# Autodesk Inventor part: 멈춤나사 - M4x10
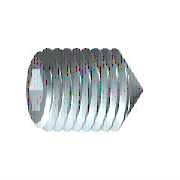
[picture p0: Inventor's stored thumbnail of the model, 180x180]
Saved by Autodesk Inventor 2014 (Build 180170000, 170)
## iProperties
Created: 2012-02
Part Number: 멈춤나사 - M4x10
Material: 강철, 연강
Description: 6각 소켓 머리 없는 멈춤 나사
Document SubType Name: Modeling
Standard: KS B 1028
Designer: mduedu
Standards Organization: KS
Language: ko-KR
Size Designation: 원추점 M4x10
Categories: <MemberInstance><Categories><Category DisplayName="조임쇠" InternalName="e4da775c-781d-43d5-af7c-5136215cf5a6" Mnemonic="FSTN"><Category DisplayName="볼트" InternalN
Density: 7.86 g/cm^3
Appearance: 강철
Mass: 0.792069 g
Surface Area: 1.48192 cm^2
Volume: 0.100772 cm^3
Author: mduedu
IsCustomPart: 1
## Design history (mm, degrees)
sketch "스케치1"
  geometry: L1 (0, 0)-(6.833, 0); L2 (10, 1.155)-(10, 2); L3 (10, 2)-(0, 2); L4 (10, 1.155)-(7.5, 1.155); L5 (7.5, 1.155)-(6.833, 0); L6 (0, -0.4)-(0, 2.4) reference; L7 (0, 2)-(0, 0)
  constraints: 13 end point, 3 parallel, 1 collinear, 1 perpendicular, 1 point on line
  dimensions: "d0" = 2.5 distance of L2.start L4.end (= INTI); "d1" = 60 deg angle of L5 L1; "d2" = 4 diameter of L3 L1 (= NND); "d3" = 2.3094 diameter of L4 L1 (= 1.1547 x SW); "d5" = 10 distance from line of L2 L3.end (= NLG)
revolve "본체" sketch "스케치1" stored, may be unused: angle "d6" = 90 deg
sketch "스케치2"
  geometry: L1 (-0.577, 1)-(0.577, 1); L2 (0.577, 1)-(1.155, 0); L3 (1.155, 0)-(0.577, -1); L4 (0.577, -1)-(-0.577, -1); L5 (-0.577, -1)-(-1.155, 0); L6 (-1.155, 0)-(-0.577, 1); 3 further points
  constraints: 12 end point, 1 coincident, 1 horizontal, 13 other
extrude "슬롯" join sketch "스케치2" taper "d7" = 0 deg; stored distance "d21" = 10
workaxis "Work Axis1"
workplane "Work Plane1"
body "Solid1"
feature "스레드" dims "d12" = 10 (= NLG), "d13" = 0
chamfer "모따기1" distance "d8" = 1.8 (computed from NND, SPD, FAWI); stored, may be unused: angle "d9" = 45 deg (= FAWI), second distance "d34" = 1.8 (computed from NND, SPD, FAWI)
chamfer "모따기2" distance "d10" = 0.42941 (= -0.5 x GD1 + 0.5 x NND); stored, may be unused: angle "d11" = 45 deg (= FAWI), second distance "d35" = 0.42941 (= -0.5 x GD1 + 0.5 x NND)
other parameters: "NND" = 4 [user parameter; used in 5 equation terms], "NLG" = 10 [user parameter; used in 2 equation terms], "INTI" = 2.5 [user parameter; used in 1 equation term], "FAWI" = 45 deg [user parameter; used in 4 equation terms], "SW" = 2 [user parameter; used in 2 equation terms], "GD1" = 3.14117 (= THREADDIA - 1.2269 x PTC) [user parameter; used in 2 equation terms], "d4" = 0, "FAWI1" = 45 deg [user parameter], "SPD" = 0.4 [user parameter; used in 2 equation terms], "d36" = 0, "d37" = 0, "GUL" = 0.42941 (= 0.61345 x PTC) [user parameter], "TPU" = 14.28571 (computed from PTC) [user parameter], "TOA" = 30 deg [user parameter], "THREADDIA" = 4 [user parameter; used in 1 equation term], "PTC" = 0.7 [user parameter; used in 4 equation terms], "GAL" = 0.42941 (= 0.61345 x PTC) [user parameter], "E0" = 2.31 (= 1.155 x SW) [user parameter]
